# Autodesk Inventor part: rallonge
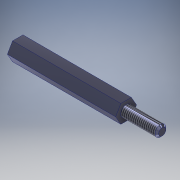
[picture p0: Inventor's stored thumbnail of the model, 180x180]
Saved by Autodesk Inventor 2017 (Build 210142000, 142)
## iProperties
Part Number: rallonge
Material: Générique
Document SubType Name: Modeling
Designer: Bruno
Density: 1 g/cm^3
Appearance: Chrome - Bleu poli
Author: Bruno
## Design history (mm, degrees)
sketch "Esquisse1"
  geometry: L1 (-2.887, 0)-(-1.443, 2.5); L2 (-1.443, 2.5)-(1.443, 2.5); L3 (1.443, 2.5)-(2.887, 0); L4 (2.887, 0)-(1.443, -2.5); L5 (1.443, -2.5)-(-1.443, -2.5); L6 (-1.443, -2.5)-(-2.887, 0); 2 further points
  constraints: 12 end point, 1 coincident, 13 other
  dimensions: "d0" = 5 distance between parallel lines of L5 L2
extrude "Extrusion1" new body sketch "Esquisse1" distance "d1" = 30; taper "d2" = 0 deg
sketch "Esquisse2"
  geometry: C1 r 1.5 at (0, 0); 1 further point
  constraints: 1 centre point, 1 coincident
  dimensions: "d3" = 3 diameter of C1
extrude "Extrusion2" join sketch "Esquisse2" distance "d4" = 10; taper "d5" = 0 deg
chamfer "Chanfrein1" distance "d6" = 0.5; stored, may be unused: second distance "d7" = 2, angle "d8" = 45 deg
feature "Filetage1" dims "d9" = 10, "d10" = 0
sketch "Esquisse3"
  geometry: C1 r 1.5 at (0, 0); 1 further point
  constraints: 1 centre point, 1 coincident
  dimensions: "d11" = 3 diameter of C1
extrude "Extrusion3" cut sketch "Esquisse3" distance "d12" = 18; taper "d13" = 0 deg
chamfer "Chanfrein2" distance "d14" = 0.5; stored, may be unused: second distance "d15" = 2, angle "d16" = 45 deg
feature "Filetage2" dims "d17" = 10, "d18" = 0
node "Solide1"
